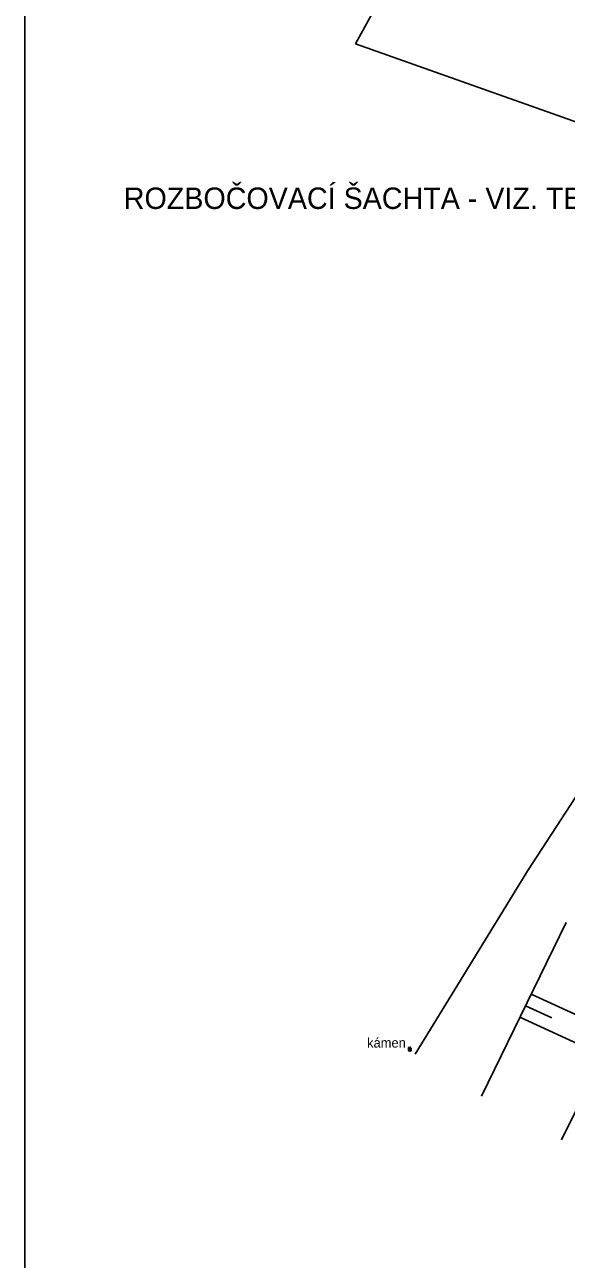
# Model space of a CAD drawing. Extents: x -517788 to -517166, y -1177087 to -1176790.
# Drawn here: x -517788 to -517762.8, y -1177027.2 to -1176969.6 of the extents above; entities that cross this region are included whole.
import ezdxf

# ---------------------------------------------------------------- set-up
doc = ezdxf.new("R2010")
doc.units = 0
for name, color, linetype in [('chodníky_obrubnik_schody', 7, 'Continuous'), ('hrany svahu', 7, 'Continuous'), ('mapove znacky', 7, 'Continuous'), ('označení lomového bodu', 7, 'Continuous'), ('porost', 7, 'Continuous'), ('Povrchy_popis', 7, 'Continuous'), ('šrafy', 7, 'Continuous')]:
    doc.layers.add(name, color=color, linetype=linetype)

msp = doc.modelspace()

# ---------------------------------------------------------------- linework, layer by layer
at = {"layer": 'chodníky_obrubnik_schody'}
msp.add_line((-517758.69, -1177012.94), (-517763, -1177021.61), dxfattribs=at)
at = {"layer": 'hrany svahu'}
msp.add_line((-517766.73, -1177019.56), (-517762.77, -1177011.47), dxfattribs=at)
msp.add_lwpolyline([(-517737.9, -1176972.12), (-517746.54, -1176968.19), (-517749.83, -1176966.57), (-517757.29, -1176963.26), (-517761.56, -1176961.09), (-517763.85, -1176960.5), (-517766.72, -1176961.07), (-517768.41, -1176962.82), (-517772.6, -1176970.47)], dxfattribs=at)
at = {"layer": 'mapove znacky'}
for radius in [0.0683, 0.0119]:
    msp.add_circle((-517770.07, -1177017.4), radius, dxfattribs=at)
msp.add_arc((-517770.07, -1177017.346), 0.0652, 339.29907, 201.87982, dxfattribs=at)
at = {"layer": 'označení lomového bodu'}
msp.add_lwpolyline([(-517788.034, -1177087.222), (-517578.034, -1177087.222), (-517578.034, -1176938.722), (-517788.034, -1176938.722)], close=True, dxfattribs=at)
at = {"layer": 'porost'}
for p, q in [((-517772.6, -1176970.47), (-517760.92, -1176974.6)), ((-517757.21, -1176997.73), (-517764.57, -1177009.04)), ((-517764.57, -1177009.04), (-517769.82, -1177017.61))]:
    msp.add_line(p, q, dxfattribs=at)
at = {"layer": 'šrafy'}
for p, q in [((-517764.405, -1177014.809), (-517760.508, -1177016.596)), ((-517764.668, -1177015.348), (-517763.447, -1177015.908)), ((-517764.932, -1177015.887), (-517761.042, -1177017.671))]:
    msp.add_line(p, q, dxfattribs=at)

# ---------------------------------------------------------------- texts
at = {"layer": 'označení lomového bodu'}
msp.add_text('ROZBOČOVACÍ ŠACHTA - VIZ. TECHNICKÁ ZPRÁVA', height=1, rotation=360, dxfattribs=at).set_placement((-517783.412, -1176978.17))
at = {"layer": 'Povrchy_popis'}
msp.add_text('kámen', height=0.45, dxfattribs=at).set_placement((-517772.063, -1177017.302))

doc.saveas('drawing.dxf')
